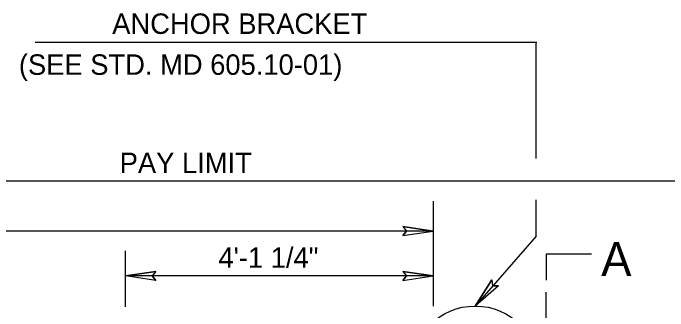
# Model space of a CAD drawing. Extents: x 12.2 to 54.5, y -7.8 to 16.1.
# Drawn here: x 13.367 to 15.289, y 15.27 to 16.143 of the extents above; entities that cross this region are included whole.
import ezdxf

# ---------------------------------------------------------------- set-up
doc = ezdxf.new("R2010")
doc.units = 0
for name, color, linetype in [('DETAIL DIM', 7, 'Continuous'), ('DETL-DIMS', 7, 'Continuous'), ('DETL-NOTE', 7, 'Continuous'), ('DETL-TITL', 7, 'Continuous')]:
    doc.layers.add(name, color=color, linetype=linetype)

msp = doc.modelspace()

# ---------------------------------------------------------------- linework, layer by layer
at = {"layer": 'DETAIL DIM'}
msp.add_circle((14.7234, 15.0957), 0.1886, dxfattribs=at)
at = {"layer": 'DETL-DIMS'}
for p, q in [((14.9049, 16.0573), (13.4317, 16.0573)), ((14.9024, 15.717), (14.9024, 16.0573)), ((15.8032, 15.6501), (12.6898, 15.6501)), ((14.6003, 15.5919), (14.6003, 15.2836)), ((14.9024, 15.4887), (14.9024, 15.5958)), ((14.5107, 15.5174), (14.6003, 15.5042)), ((14.5107, 15.5174), (14.5218, 15.5042)), ((14.6003, 15.5042), (12.8606, 15.5042)), ((14.5107, 15.4913), (14.6003, 15.5042)), ((14.5107, 15.4913), (14.5218, 15.5042)), ((14.9024, 15.4887), (14.7234, 15.2843)), ((13.6965, 15.2824), (13.6965, 15.4463)), ((14.9316, 15.436), (14.9316, 15.3602)), ((15.065, 15.436), (14.9319, 15.436)), ((13.7861, 15.3856), (13.6965, 15.3724)), ((13.7861, 15.3856), (13.775, 15.3724)), ((14.5107, 15.3856), (14.6003, 15.3724)), ((14.5107, 15.3856), (14.5218, 15.3724)), ((14.6003, 15.3724), (13.6965, 15.3724)), ((13.7861, 15.3595), (13.6965, 15.3724)), ((13.7861, 15.3595), (13.775, 15.3724)), ((14.5107, 15.3595), (14.6003, 15.3724)), ((14.5107, 15.3595), (14.5218, 15.3724)), ((14.7719, 15.3608), (14.7234, 15.2843)), ((14.7917, 15.3437), (14.7234, 15.2843)), ((14.7719, 15.3608), (14.7746, 15.3437)), ((14.7917, 15.3437), (14.7746, 15.3437)), ((14.931, 15.3251), (14.931, 14.9461))]:
    msp.add_line(p, q, dxfattribs=at)
for points in [[(14.5107, 15.4913), (14.6003, 15.5042), (14.5107, 15.5174), (14.5218, 15.5042)], [(13.7861, 15.3595), (13.6965, 15.3724), (13.7861, 15.3856), (13.775, 15.3724)], [(14.5107, 15.3595), (14.6003, 15.3724), (14.5107, 15.3856), (14.5218, 15.3724)], [(14.7917, 15.3437), (14.7234, 15.2843), (14.7719, 15.3608), (14.7746, 15.3437)]]:
    msp.add_lwpolyline(points, close=True, dxfattribs=at)

# ---------------------------------------------------------------- texts
at = {"layer": 'DETL-NOTE'}
for s, p in [('ANCHOR BRACKET', (13.6579, 16.0821)), ('(SEE STD. MD 605.10-01)', (13.3838, 15.9621)), ('PAY LIMIT', (13.6798, 15.674)), ('4\'-1 1/4"', (13.9697, 15.3963))]:
    msp.add_text(s, height=0.06, dxfattribs=at).set_placement(p)
at = {"layer": 'DETL-TITL'}
msp.add_text('A', height=0.1, rotation=360, dxfattribs=at).set_placement((15.0934, 15.372))

doc.saveas('drawing.dxf')
